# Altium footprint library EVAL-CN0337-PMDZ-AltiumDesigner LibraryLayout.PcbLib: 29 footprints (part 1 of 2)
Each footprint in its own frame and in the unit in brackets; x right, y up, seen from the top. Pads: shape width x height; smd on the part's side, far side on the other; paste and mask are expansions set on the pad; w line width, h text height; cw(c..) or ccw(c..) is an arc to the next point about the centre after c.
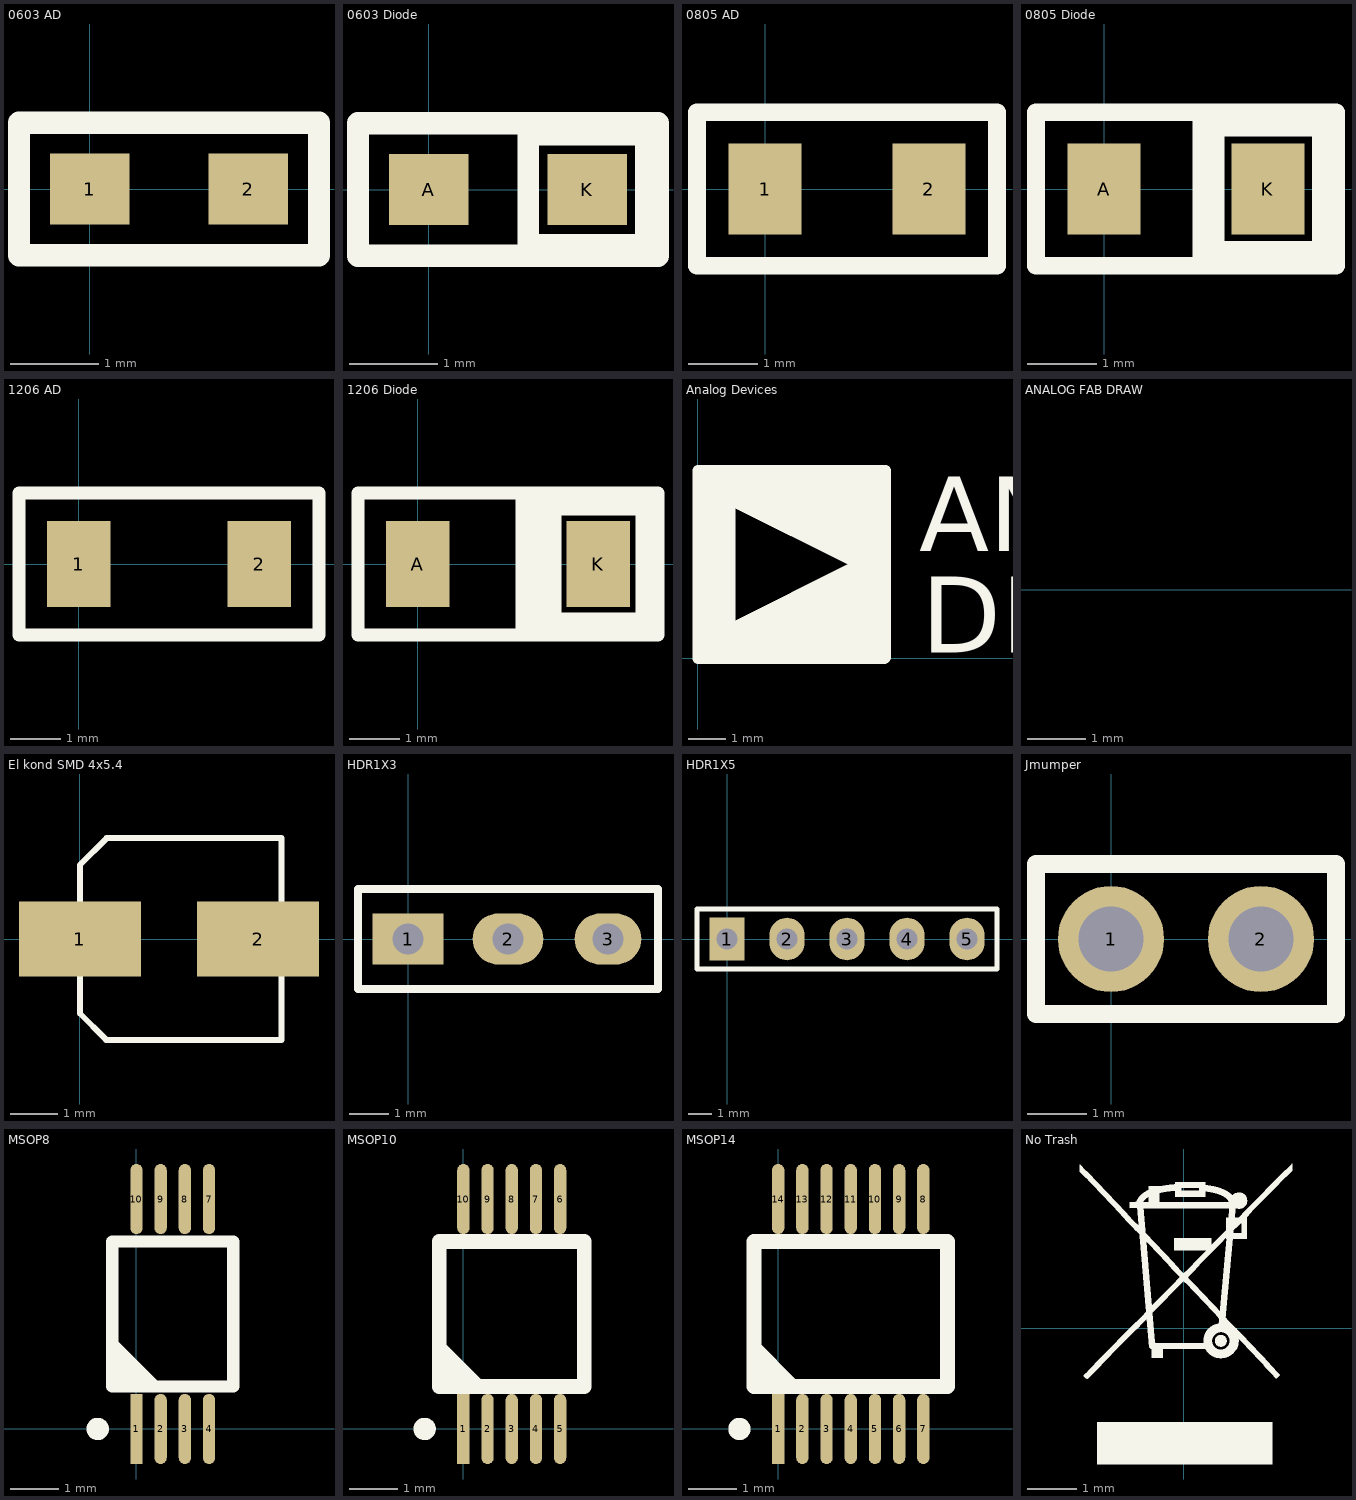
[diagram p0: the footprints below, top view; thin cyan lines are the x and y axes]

## 0603 AD [mm]
pads (2):
  rect 0.9x0.8 smd: 1(0,0) 2(1.8,0)
Top Overlay:
  lines w0.254: -0.8,-0.75 2.6,-0.75 2.6,0.75 -0.8,0.75 -0.8,-0.75

## 0603 Diode [mm]
pads (2):
  rect 0.9x0.8 smd: A(0,0) K(1.8,0)
Top Overlay:
  rectangle: 1.19,-0.75 2.6,-0.502
  rectangle: 2.341,-0.75 2.6,0.762
  rectangle: 1.213,0.5 2.6,0.75
  rectangle: 1.01,-0.75 1.253,0.75
  lines w0.254: -0.8,-0.75 2.6,-0.75 2.6,0.75 -0.8,0.75 -0.8,-0.75

## 0805 AD [mm]
pads (2):
  rect 1.05x1.3 smd: 1(0,0) 2(2.35,0)
Top Overlay:
  lines w0.254: -0.975,-1.1 -0.975,1.1 3.325,1.1 3.325,-1.1 -0.975,-1.1

## 0805 Diode [mm]
pads (2):
  rect 1.05x1.3 smd: A(0,0) K(2.35,0)
Top Overlay:
  rectangle: 1.271,-1.1 1.726,1.1
  rectangle: 1.657,0.752 3.325,1.1
  rectangle: 2.979,-1.1 3.325,0.859
  rectangle: 1.368,-1.1 3.017,-0.746
  lines w0.254: -0.975,-1.1 3.325,-1.1 3.325,1.1 -0.975,1.1 -0.975,-1.1

## 1206 AD [mm]
pads (2):
  rect 1.25x1.7 smd: 1(0,0) 2(3.55,0)
Top Overlay:
  lines w0.254: -1.175,-1.4 -1.175,1.4 4.725,1.4 4.725,-1.4 -1.175,-1.4

## 1206 Diode [mm]
pads (2):
  rect 1.25x1.7 smd: A(0,0) K(3.55,0)
Top Overlay:
  rectangle: 2.68,-1.4 4.504,-0.951
  rectangle: 4.278,-1.4 4.725,1.085
  rectangle: 2.748,0.955 4.725,1.4
  rectangle: 1.925,-1.4 2.826,1.4
  lines w0.254: -1.175,-1.4 4.725,-1.4 4.725,1.4 -1.175,1.4 -1.175,-1.4

## Analog Devices [mil]
Top Overlay:
  region: 40,40 160,100 199,101 199,2 0,1 0,64
  region: 40,160 160,100 201,99 201,200 -1,201 0,144
  region: 40,40 40,160 -1,160 1,40
  lines w12: 0,0 199,0 200,1 200,200 0,200 0,0
  text "DEVICES" at 238,6 h81
  text "ANALOG" at 236,114 h80

## ANALOG FAB DRAW [mil]
Drill Drawing:
  region: -245,77 -125,17 -84,16 -84,117 -286,118 -285,61
  region: -245,-43 -245,77 -286,77 -284,-43
  region: -245,-43 -125,17 -86,18 -86,-81 -285,-82 -285,-19
  lines w12: -86,-83 -285,-83 -285,117 -85,117 -85,-82
  text "ANALOG" at -49,31 h80
  text "DEVICES" at -47,-77 h81

## El kond SMD 4x5.4 [mm]
pads (2):
  rect 2.6x1.6 smd: 1(0,0) 2(3.8,0)
Top Overlay:
  lines w0.127: 0.54,-2.13 0,-1.59 ; 0,-1.59 0,1.58 ; 0,-1.59 0.56,-2.15 4.3,-2.15 4.3,2.15 0.57,2.15 ; 0,1.58 0,1.58 ; 0,1.58 0.57,2.15 ; 0,1.58 0.57,2.15

## HDR1X3 [mm] "Connector; Header; 3 Position"
pads (3):
  rect 1.8x1.3 hole 0.8: 1(0,0)
  oval 1.8x1.3 hole 0.8: 2(2.54,0)
  oval 1.7x1.3 hole 0.8: 3(5.08,0)
Top Overlay:
  lines w0.2: -1.27,-1.27 6.35,-1.27 6.35,1.27 -1.27,1.27 -1.27,-1.27

## HDR1X5 [mm] "Connector; Header; 5 Position"
height 1.75
pads (5):
  rect 1.5x1.8 hole 0.9: 1(0,0)
  oval 1.5x1.8 hole 0.9: 2(2.54,0) 3(5.08,0) 4(7.62,0) 5(10.16,0)
Top Overlay:
  lines w0.2: -1.27,-1.27 -1.27,1.27 11.43,1.27 11.43,-1.27 -1.27,-1.27

## Jmumper [mm]
pads (2):
  round 1.8 hole 1.1: 1(0,0) 2(2.54,0)
Top Overlay:
  lines w0.3: -1.27,-1.27 3.81,-1.27 3.81,1.27 -1.27,1.27 -1.27,-1.27

## MSOP8 [mm]
pads (8):
  rect 0.254x1.45 smd: 1(0,0)
  oval 0.254x1.45 smd: 2(0.5,0) 3(1,0) 4(1.5,0) 7(1.5,4.75) 8(1,4.75) 9(0.5,4.75) 10(0,4.75)
Top Overlay:
  circle w0.3: c-0.8,0 r0.08
  rectangle: -0.5,0.944 -0.186,1.111
  region: 0.552,0.875 -0.386,1.815 -0.387,1.815 -0.387,1.013 0.015,0.875
  lines w0.25: -0.5,0.875 -0.5,3.875 1.94,3.875 ; -0.49,0.875 2,0.875 2,3.875

## MSOP10 [mm]
pads (10):
  rect 0.254x1.45 smd: 1(0,0)
  oval 0.254x1.45 smd: 2(0.5,0) 3(1,0) 4(1.5,0) 5(2,0) 6(2,4.75) 7(1.5,4.75) 8(1,4.75) 9(0.5,4.75) 10(0,4.75)
Top Overlay:
  circle w0.3: c-0.8,0 r0.08
  region: 0.439,0.941 -0.499,1.881 -0.5,1.881 -0.5,1.079 -0.098,0.941
  lines w0.305: -0.5,0.875 -0.5,3.875 2.5,3.875 2.5,0.875 -0.5,0.875

## MSOP14 [mm]
pads (14):
  rect 0.254x1.45 smd: 1(0,0)
  oval 0.254x1.45 smd: 2(0.5,0) 3(1,0) 4(1.5,0) 5(2,0) 6(2.5,0) 7(3,0) 8(3,4.75) 9(2.5,4.75) 10(2,4.75) 11(1.5,4.75) 12(1,4.75) 13(0.5,4.75) 14(0,4.75)
Top Overlay:
  circle w0.3: c-0.8,0 r0.08
  region: 0.439,0.941 -0.499,1.881 -0.5,1.881 -0.5,1.079 -0.098,0.941
  lines w0.305: 3.48,0.875 -0.5,0.875 -0.5,3.875 3.48,3.875 ; 3.497,0.875 3.497,3.875

## No Trash [mil]
Top Overlay:
  drawing of 1555 lines, arcs and shapes, not listed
